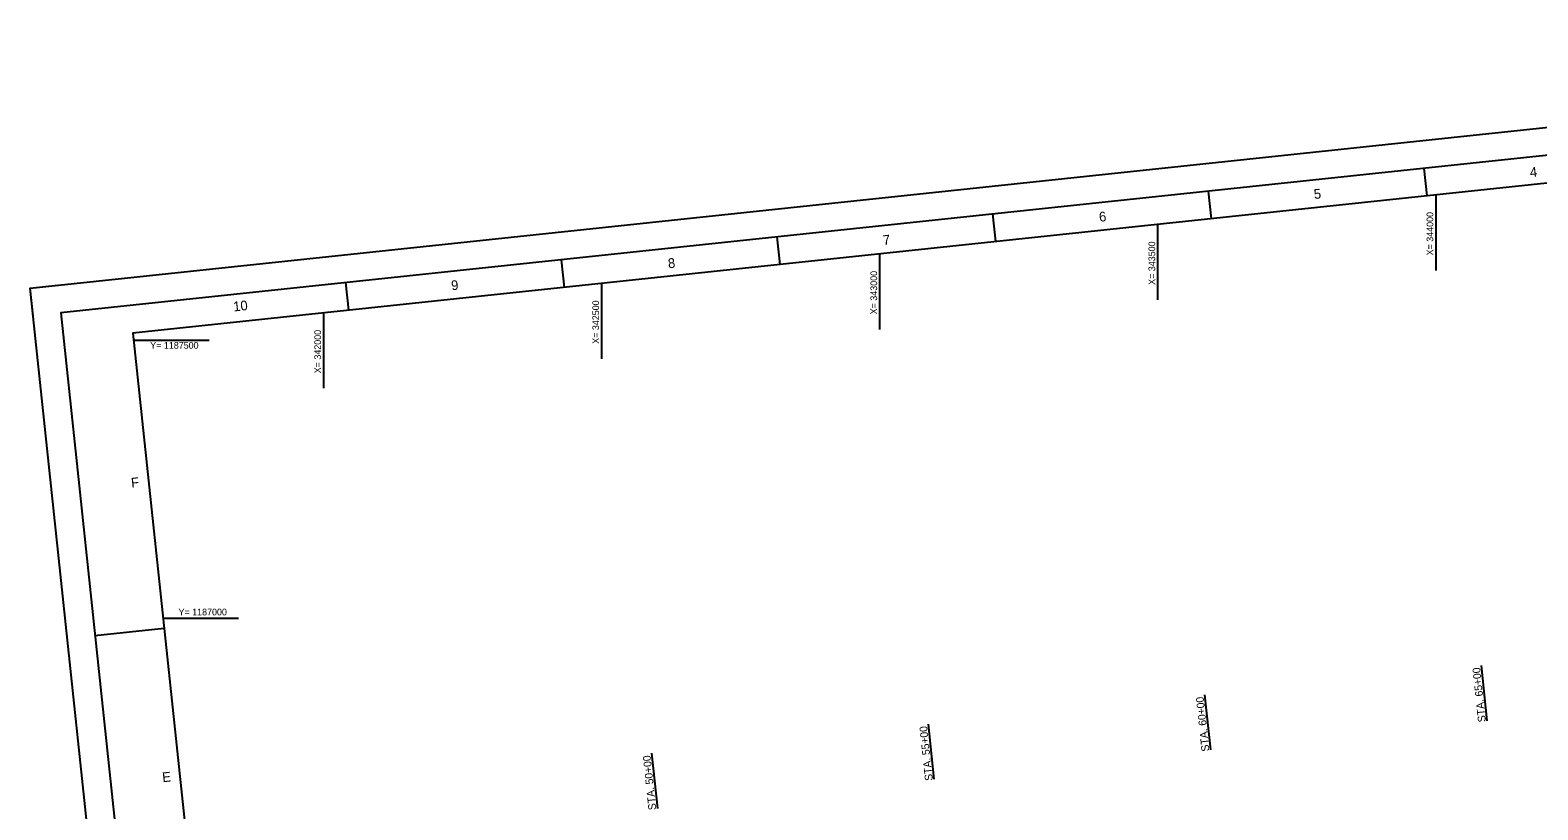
# Model space of a CAD drawing. Extents: x 341472 to 346206, y 1184213 to 1188058.
# Drawn here: x 341472 to 344183, y 1186655 to 1188058 of the extents above; entities that cross this region are included whole.
import ezdxf

# ---------------------------------------------------------------- set-up
doc = ezdxf.new("R2010")
doc.units = 0
for name, color, linetype in [('G-ANNO-NPLT', 7, 'Continuous'), ('G-ANNO-TTLB', 7, 'Continuous'), ('V-ALGN-TEXT', 7, 'Continuous'), ('V-TOPO-COOR-STAT', 7, 'Continuous')]:
    doc.layers.add(name, color=color, linetype=linetype)

msp = doc.modelspace()

# ---------------------------------------------------------------- linework, layer by layer
at = {"layer": 'G-ANNO-NPLT'}
msp.add_lwpolyline([(341472, 1187593.7), (345847.5, 1188057.5), (346205.9, 1184676.5), (341830.4, 1184212.7)], close=True, dxfattribs=at)
msp.add_lwpolyline([(341477.3, 1187544), (341472, 1187593.7), (341521.7, 1187599)], dxfattribs=at)
at = {"layer": 'G-ANNO-TTLB'}
for p, q in [((343978.3, 1187809.1), (343983.5, 1187759.4)), ((343590.4, 1187768), (343595.7, 1187718.3)), ((343202.6, 1187726.9), (343207.9, 1187677.2)), ((342814.8, 1187685.8), (342820.1, 1187636)), ((342427, 1187644.7), (342432.2, 1187594.9)), ((342427, 1187644.7), (342432.2, 1187594.9)), ((342039.1, 1187603.5), (342044.4, 1187553.8)), ((341588.5, 1186969), (341712.8, 1186982.2))]:
    msp.add_line(p, q, dxfattribs=at)
for points in [[(341874.8, 1184267.7), (346150.9, 1184720.9), (345803, 1188002.5), (341527, 1187549.3)], [(345758.6, 1187947.5), (341656.6, 1187512.7), (341993.9, 1184330.6), (346095.9, 1184765.4)]]:
    msp.add_lwpolyline(points, close=True, dxfattribs=at)
at = {"layer": 'V-ALGN-TEXT'}
for p, q in [((344092.2, 1186815.6), (344081.6, 1186915)), ((343595, 1186762.9), (343584.4, 1186862.3)), ((343097.8, 1186710.2), (343087.2, 1186809.6)), ((342600.5, 1186657.5), (342590, 1186756.9))]:
    msp.add_line(p, q, dxfattribs=at)
at = {"layer": 'V-TOPO-COOR-STAT'}
for p, q in [((344000, 1187625.4), (344000, 1187761.1)), ((343500, 1187572.4), (343500, 1187708.1)), ((343000, 1187519.4), (343000, 1187655.1)), ((342500, 1187466.4), (342500, 1187602.1)), ((342000, 1187413.4), (342000, 1187549.1)), ((341657.9, 1187500), (341793.7, 1187500)), ((341710.9, 1187000), (341846.7, 1187000))]:
    msp.add_line(p, q, dxfattribs=at)

# ---------------------------------------------------------------- texts
at = {"layer": 'G-ANNO-TTLB'}
for s, p in [('4', (344169.7, 1187793)), ('5', (343781.2, 1187753.7)), ('6', (343394.9, 1187712.8)), ('7', (343006.3, 1187670.9)), ('8', (342619.8, 1187629.2)), ('9', (342230, 1187589.5)), ('10', (341838.1, 1187551.5)), ('F', (341654.4, 1187234.6)), ('E', (341710.4, 1186704.8))]:
    msp.add_text(s, height=17.5, rotation=6.0506, dxfattribs=at).set_placement(p)
at = {"layer": 'V-ALGN-TEXT'}
for s, p in [('STA. 65+00', (344089.6, 1186813.6)), ('STA. 60+00', (343592.4, 1186760.9)), ('STA. 55+00', (343095.2, 1186708.2)), ('STA. 50+00', (342597.9, 1186655.5))]:
    msp.add_text(s, height=13.92, rotation=96.0506, dxfattribs=at).set_placement(p)
at = {"layer": 'V-TOPO-COOR-STAT'}
for s, p in [('X= 344000', (343995, 1187652.4)), ('X= 343500', (343495, 1187599.4)), ('X= 343000', (342995, 1187546.4)), ('X= 342500', (342495, 1187493.4)), ('X= 342000', (341995, 1187440.4))]:
    msp.add_text(s, height=12, rotation=90, dxfattribs=at).set_placement(p)
for s, p in [('Y= 1187500', (341687.9, 1187484.6)), ('Y= 1187000', (341738.8, 1187005))]:
    msp.add_text(s, height=12, dxfattribs=at).set_placement(p)

doc.saveas('drawing.dxf')
